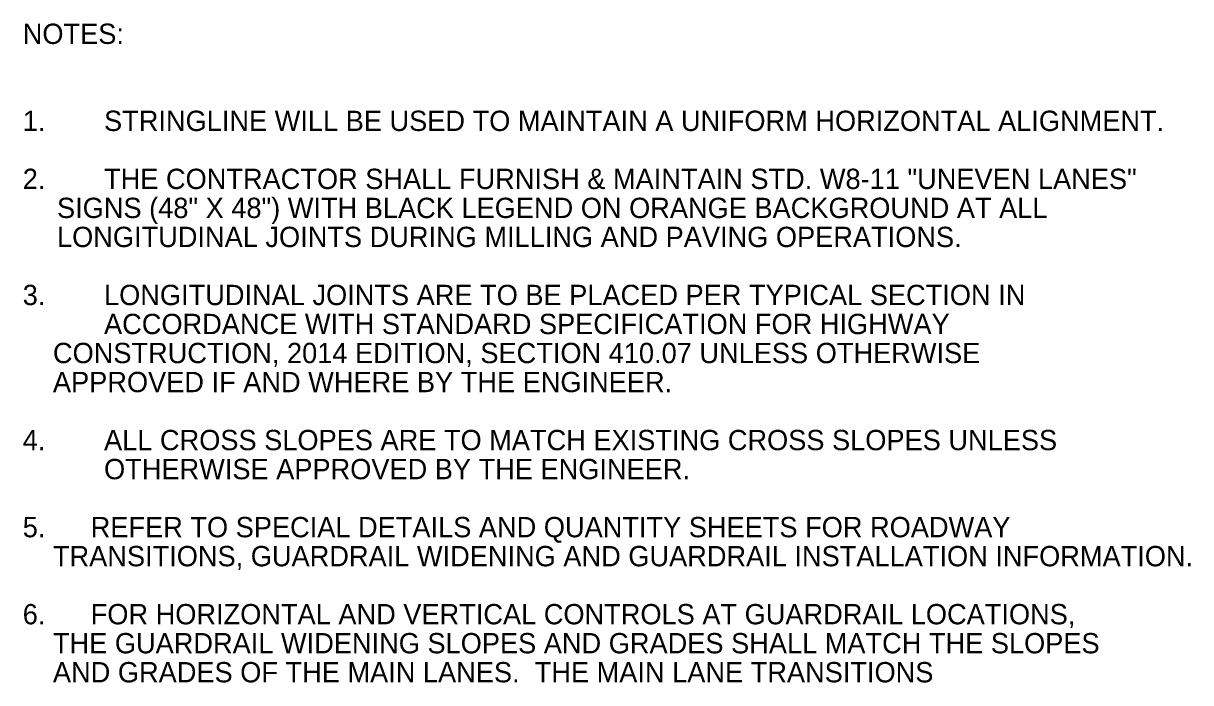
# Model space of a CAD drawing. Extents: x 545241 to 1930787, y -1971772 to 596640.
# Drawn here: x 547787.9 to 548189.9, y -1947959 to -1947731.8 of the extents above; entities that cross this region are included whole.
import ezdxf

# ---------------------------------------------------------------- set-up
doc = ezdxf.new("R2010")
doc.units = 0
doc.layers.add('R_Border Notes', color=7, linetype='Continuous')

msp = doc.modelspace()

# ---------------------------------------------------------------- texts
at = {"layer": 'R_Border Notes'}
for s, p in [('NOTES: ', (547787.69, -1947738.87)), ('1.', (547787.69, -1947768.87)), ('STRINGLINE WILL BE USED TO MAINTAIN A UNIFORM HORIZONTAL ALIGNMENT.', (547815.69, -1947768.87)), ('2.', (547787.69, -1947788.87)), ('THE CONTRACTOR SHALL FURNISH & MAINTAIN STD. W8-11 "UNEVEN LANES" ', (547815.69, -1947788.87)), ('    SIGNS (48" X 48") WITH BLACK LEGEND ON ORANGE BACKGROUND AT ALL ', (547789.09, -1947798.87)), ('    LONGITUDINAL JOINTS DURING MILLING AND PAVING OPERATIONS.', (547789.09, -1947808.87)), ('3.', (547787.69, -1947828.87)), ('LONGITUDINAL JOINTS ARE TO BE PLACED PER TYPICAL SECTION IN ', (547815.69, -1947828.87)), ('ACCORDANCE WITH STANDARD SPECIFICATION FOR HIGHWAY', (547815.69, -1947838.87)), ('    CONSTRUCTION, 2014 EDITION, SECTION 410.07 UNLESS OTHERWISE', (547787.69, -1947848.87)), ('    APPROVED IF AND WHERE BY THE ENGINEER.', (547787.69, -1947858.87)), ('4.', (547787.69, -1947878.87)), ('ALL CROSS SLOPES ARE TO MATCH EXISTING CROSS SLOPES UNLESS ', (547815.69, -1947878.87)), ('OTHERWISE APPROVED BY THE ENGINEER.', (547815.69, -1947888.87)), ('5.      REFER TO SPECIAL DETAILS AND QUANTITY SHEETS FOR ROADWAY', (547787.69, -1947908.87)), ('    TRANSITIONS, GUARDRAIL WIDENING AND GUARDRAIL INSTALLATION INFORMATION.', (547787.69, -1947918.87)), ('6.      FOR HORIZONTAL AND VERTICAL CONTROLS AT GUARDRAIL LOCATIONS,', (547787.69, -1947938.87)), ('    THE GUARDRAIL WIDENING SLOPES AND GRADES SHALL MATCH THE SLOPES', (547787.69, -1947948.87)), ('    AND GRADES OF THE MAIN LANES.  THE MAIN LANE TRANSITIONS', (547787.69, -1947958.87))]:
    msp.add_text(s, height=7, dxfattribs=at).set_placement(p)

doc.saveas('drawing.dxf')
